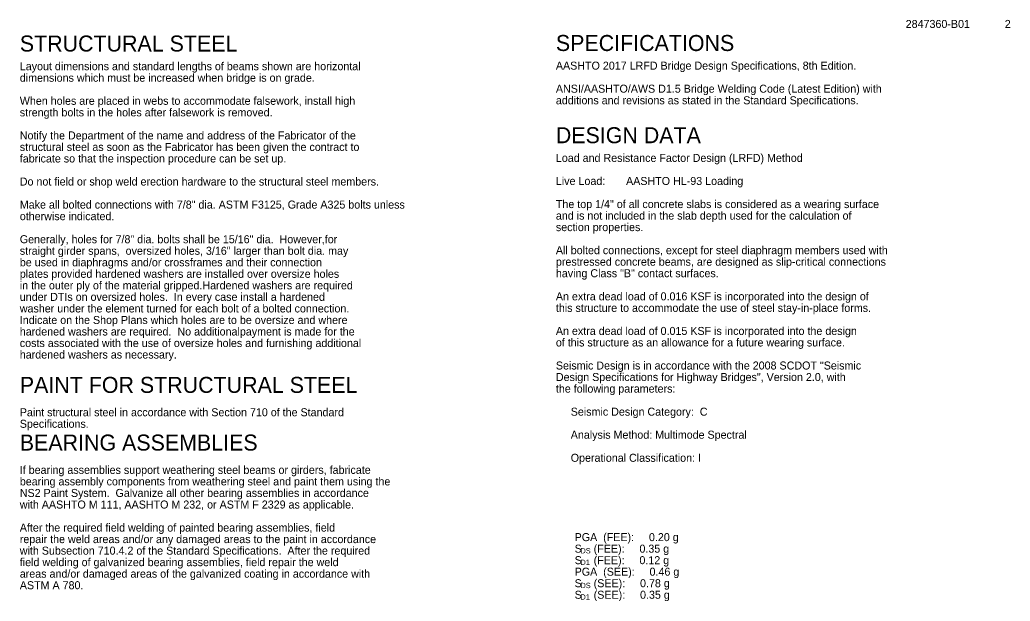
# Model space of a CAD drawing. Extents: x 0.5 to 33.9, y 1.3 to 22.
# Drawn here: x 18.35 to 33.82, y 12.49 to 21.56 of the extents above; entities that cross this region are included whole.
import ezdxf

# ---------------------------------------------------------------- set-up
doc = ezdxf.new("R2010")
doc.units = 0
doc.layers.add('BR_TEXT', color=7, linetype='Continuous')

msp = doc.modelspace()

# ---------------------------------------------------------------- texts
at = {"layer": 'BR_TEXT'}
for s, height, p in [('2847360-B01', 0.125, (32.19, 21.437)), ('2', 0.125, (33.738, 21.437)), ('STRUCTURAL STEEL', 0.25, (18.35, 21.069)), ('SPECIFICATIONS', 0.25, (26.725, 21.077)), ('Layout dimensions and standard lengths of beams shown are horizontal ', 0.125, (18.35, 20.777)), ('AASHTO 2017 LRFD Bridge Design Specifications, 8th Edition.', 0.125, (26.725, 20.786)), ('dimensions which must be increased when bridge is on grade.', 0.125, (18.35, 20.597)), ('ANSI/AASHTO/AWS D1.5 Bridge Welding Code (Latest Edition) with', 0.125, (26.725, 20.426)), ('When holes are placed in webs to accommodate falsework, install high', 0.125, (18.35, 20.237)), ('additions and revisions as stated in the Standard Specifications.', 0.125, (26.725, 20.245)), ('strength bolts in the holes after falsework is removed.', 0.125, (18.35, 20.056)), ('Notify the Department of the name and address of the Fabricator of the ', 0.125, (18.35, 19.696)), ('DESIGN DATA', 0.25, (26.724, 19.637)), ('structural steel as soon as the Fabricator has been given the contract to ', 0.125, (18.35, 19.516)), ('fabricate so that the inspection procedure can be set up.', 0.125, (18.35, 19.336)), ('Load and Resistance Factor Design (LRFD) Method', 0.125, (26.725, 19.345)), ('Do not field or shop weld erection hardware to the structural steel members. ', 0.125, (18.35, 18.976)), ('Live Load:       AASHTO HL-93 Loading ', 0.125, (26.725, 18.985)), ('Make all bolted connections with 7/8" dia. ASTM F3125, Grade A325 bolts unless', 0.125, (18.35, 18.616)), ('The top 1/4" of all concrete slabs is considered as a wearing surface ', 0.125, (26.725, 18.624)), ('otherwise indicated.', 0.125, (18.35, 18.435)), ('and is not included in the slab depth used for the calculation of ', 0.125, (26.725, 18.444)), ('section properties.', 0.125, (26.725, 18.264)), ('Generally, holes for 7/8" dia. bolts shall be 15/16" dia.  However,for ', 0.125, (18.35, 18.075)), ('straight girder spans,  oversized holes, 3/16" larger than bolt dia. may ', 0.125, (18.35, 17.895)), ('All bolted connections, except for steel diaphragm members used with', 0.125, (26.725, 17.904)), ('be used in diaphragms and/or crossframes and their connection ', 0.125, (18.35, 17.715)), ('prestressed concrete beams, are designed as slip-critical connections', 0.125, (26.725, 17.724)), ('plates provided hardened washers are installed over oversize holes', 0.125, (18.35, 17.535)), ('having Class "B" contact surfaces.', 0.125, (26.725, 17.544)), ('in the outer ply of the material gripped.Hardened washers are required', 0.125, (18.35, 17.355)), ('under DTIs on oversized holes.  In every case install a hardened ', 0.125, (18.35, 17.175)), ('An extra dead load of 0.016 KSF is incorporated into the design of ', 0.125, (26.725, 17.183)), ('washer under the element turned for each bolt of a bolted connection.  ', 0.125, (18.35, 16.994)), ('this structure to accommodate the use of steel stay-in-place forms.', 0.125, (26.725, 17.003)), ('Indicate on the Shop Plans which holes are to be oversize and where ', 0.125, (18.35, 16.814)), ('hardened washers are required.  No additionalpayment is made for the ', 0.125, (18.35, 16.634)), ('An extra dead load of 0.015 KSF is incorporated into the design', 0.125, (26.725, 16.643)), ('costs associated with the use of oversize holes and furnishing additional ', 0.125, (18.35, 16.454)), ('of this structure as an allowance for a future wearing surface.', 0.125, (26.725, 16.463)), ('hardened washers as necessary.', 0.125, (18.35, 16.274)), ('Seismic Design is in accordance with the 2008 SCDOT "Seismic', 0.125, (26.725, 16.103)), ('PAINT FOR STRUCTURAL STEEL', 0.25, (18.35, 15.738)), ('Design Specifications for Highway Bridges", Version 2.0, with', 0.125, (26.725, 15.923)), ('the following parameters:', 0.125, (26.725, 15.742)), ('Paint structural steel in accordance with Section 710 of the Standard ', 0.125, (18.35, 15.373)), ('     Seismic Design Category:  C', 0.125, (26.725, 15.382)), ('Specifications.', 0.125, (18.35, 15.193)), ('BEARING ASSEMBLIES', 0.25, (18.35, 14.837)), ('     Analysis Method: Multimode Spectral', 0.125, (26.725, 15.022)), ('     Operational Classification: I', 0.125, (26.725, 14.662)), ('If bearing assemblies support weathering steel beams or girders, fabricate ', 0.125, (18.35, 14.473)), ('bearing assembly components from weathering steel and paint them using the ', 0.125, (18.35, 14.293)), ('NS2 Paint System.  Galvanize all other bearing assemblies in accordance ', 0.125, (18.35, 14.113)), ('with AASHTO M 111, AASHTO M 232, or ASTM F 2329 as applicable. ', 0.125, (18.35, 13.932)), ('After the required field welding of painted bearing assemblies, field ', 0.125, (18.35, 13.572)), ('repair the weld areas and/or any damaged areas to the paint in accordance ', 0.125, (18.35, 13.392)), ('PGA  (FEE):     0.20 g', 0.125, (27.018, 13.423)), ('with Subsection 710.4.2 of the Standard Specifications.  After the required ', 0.125, (18.35, 13.212)), ('S    (FEE):     0.35 g', 0.125, (27.018, 13.243)), ('DS', 0.0833, (27.109, 13.231)), ('field welding of galvanized bearing assemblies, field repair the weld ', 0.125, (18.35, 13.032)), ('S    (FEE):     0.12 g', 0.125, (27.018, 13.063)), ('PGA  (SEE):     0.46 g', 0.125, (27.018, 12.883)), ('D1', 0.0833, (27.109, 13.05)), ('areas and/or damaged areas of the galvanized coating in accordance with ', 0.125, (18.35, 12.852)), ('ASTM A 780.', 0.125, (18.35, 12.672)), ('S    (SEE):     0.78 g', 0.125, (27.018, 12.703)), ('DS', 0.0833, (27.109, 12.689)), ('S    (SEE):     0.35 g', 0.125, (27.018, 12.523)), ('D1', 0.0833, (27.109, 12.509))]:
    msp.add_text(s, height=height, dxfattribs=at).set_placement(p)

doc.saveas('drawing.dxf')
